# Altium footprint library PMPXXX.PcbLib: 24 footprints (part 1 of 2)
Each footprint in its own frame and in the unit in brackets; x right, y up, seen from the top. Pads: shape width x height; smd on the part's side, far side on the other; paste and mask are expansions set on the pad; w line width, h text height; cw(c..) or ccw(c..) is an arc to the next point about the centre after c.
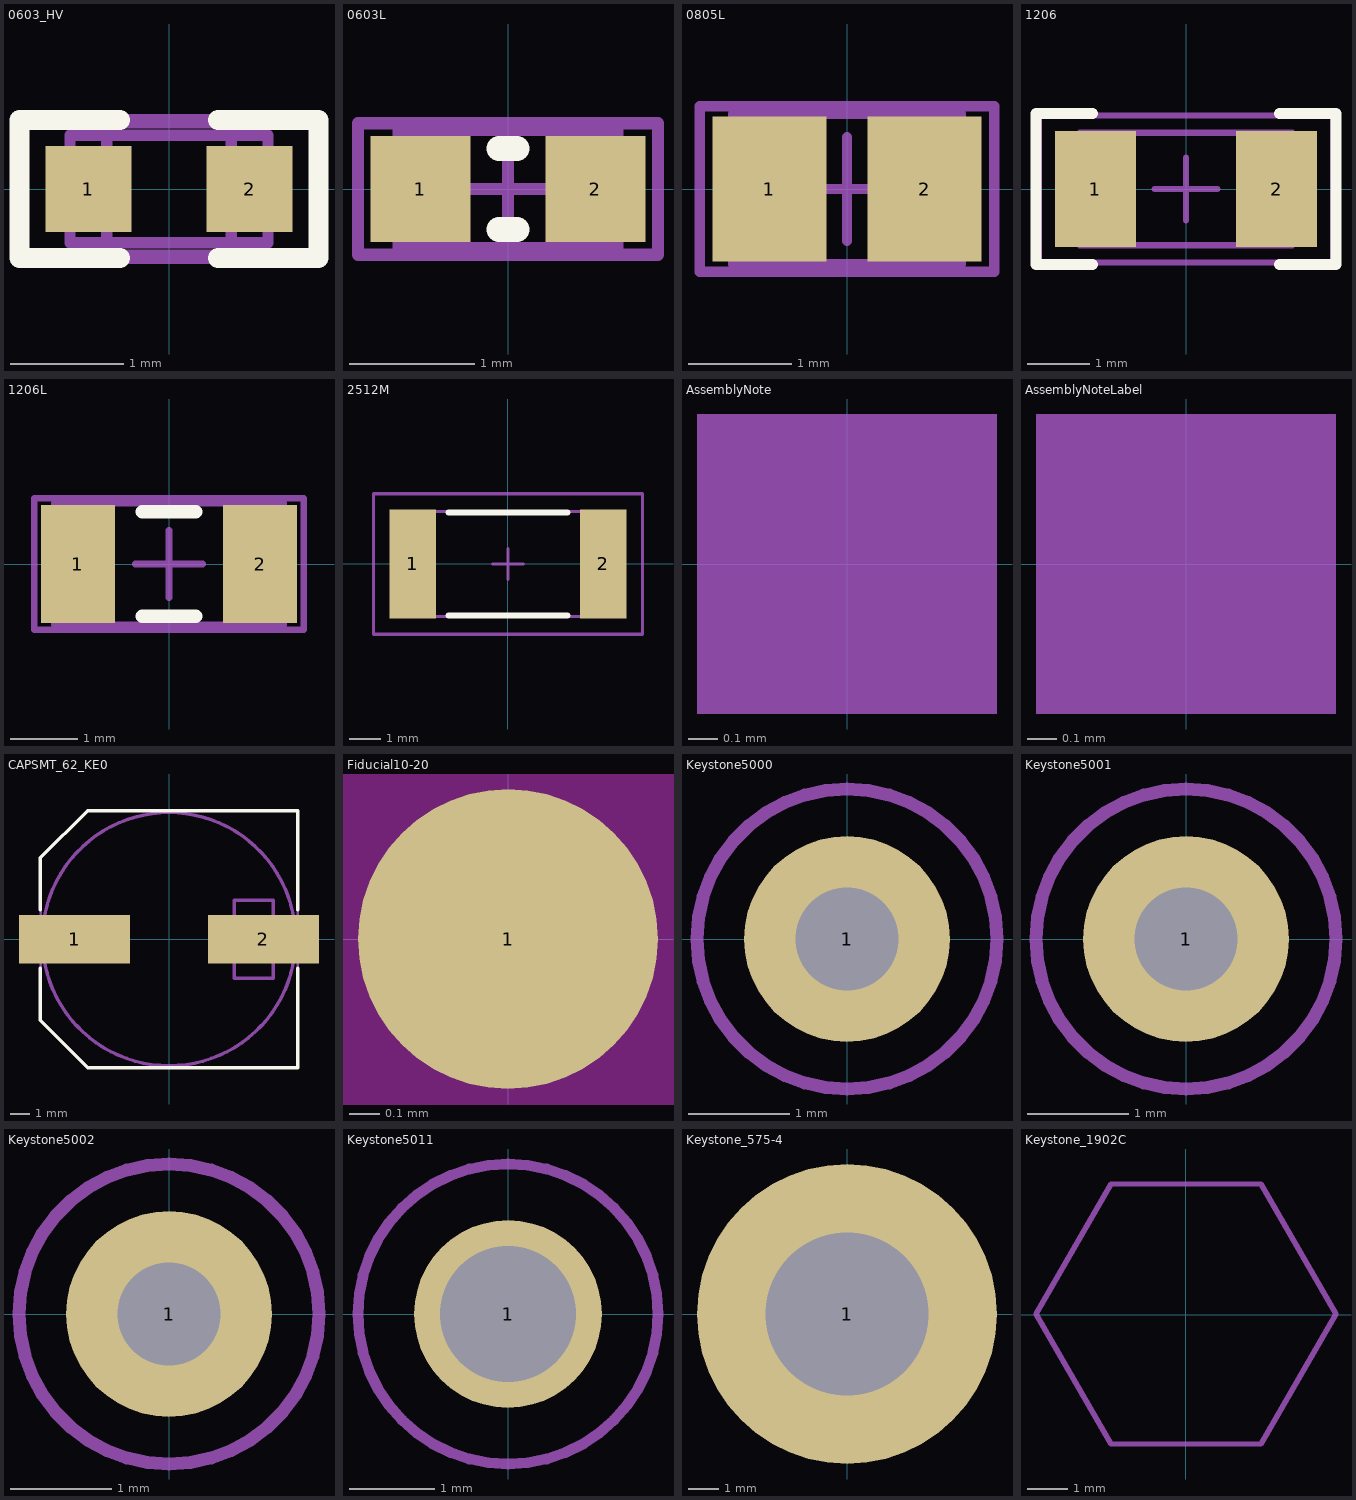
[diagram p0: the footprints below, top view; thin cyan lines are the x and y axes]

## 0603_HV [mil] "Ernesto recommended land pattern.  26 mil between pads."
height 37.4
pads (2):
  rect 30x30 smd: 1(-28,0) 2(28,0)
Top Overlay:
  lines w7: -17,-24 -52,-24 -52,0 -52,24 -17,24 ; 17,-24 52,-24 52,0 52,24 17,24
Mechanical 5:
  lines w5: -52.17,-23.62 -52.17,23.62 52.17,23.62 52.17,-23.62 -52.17,-23.62
  text ".Designator" at -45.82,-12.5 h25
Mechanical 13:
  lines w3.94: -21.65,-18.7 -21.65,18.7 ; 21.65,-18.7 21.65,18.7 ; -34.45,-18.7 -34.45,18.7 34.45,18.7 34.45,-18.7 -34.45,-18.7
3D body: height 33.46, standoff 0, extent 21.67,-18.68 34.43,18.68
3D body: height 33.46, standoff 0, extent -21.63,-18.68 21.63,18.68
3D body: height 33.46, standoff 0, extent -34.43,-18.68 -21.67,18.68

## 0603L [mm] "0603 from SM-752 data"
height 0.85
pads (2):
  rect 0.8x0.85 smd: 1(-0.7,0) 2(0.7,0)
Top Overlay:
  lines w0.2: -0.071,-0.325 0.071,-0.325 ; -0.071,0.325 0.071,0.325
Mechanical 5:
  lines w0.1: -1.2,-0.525 -1.2,0.525 1.2,0.525 1.2,-0.525 -1.2,-0.525
  text ".Designator" at -1.05,-0.275 h0.56
Mechanical 13:
  lines w0.1: -0.55,-0.475 -0.55,0.475 ; 0.55,-0.475 0.55,0.475 ; -0.875,-0.475 -0.875,0.475 0.875,0.475 0.875,-0.475 -0.875,-0.475
Mechanical 15:
  lines w0.1: -0.475,0 0.475,0 ; 0,-0.475 0,0.475 ; -1.2,-0.525 1.2,-0.525 1.2,0.525 -1.2,0.525 -1.2,-0.525
3D body: height 0.85, standoff 0, extent 0.551,-0.474 0.874,0.474
3D body: height 0.85, standoff 0, extent -0.549,-0.474 0.549,0.474
3D body: height 0.85, standoff 0, extent -0.874,-0.474 -0.551,0.474

## 0805L [mm] "0805 from SM-752 data"
height 1.1
pads (2):
  rect 1.1x1.4 smd: 1(-0.75,0) 2(0.75,0)
Mechanical 5:
  lines w0.1: -1.425,-0.8 1.425,-0.8 1.425,0.8 -1.425,0.8 -1.425,-0.8
  text ".Designator" at -1.2,-0.325 h0.64
Mechanical 13:
  lines w0.1: -0.65,-0.725 -0.65,0.725 ; 0.65,-0.725 0.65,0.725 ; -1.1,-0.725 1.1,-0.725 1.1,0.725 -1.1,0.725 -1.1,-0.725
Mechanical 15:
  lines w0.1: -0.5,0 0.5,0 ; 0,-0.5 0,0.5 ; -1.425,-0.8 -1.425,0.8 1.425,0.8 1.425,-0.8 -1.425,-0.8
3D body: height 1.1, standoff 0, extent -1.099,-0.724 -0.651,0.724
3D body: height 1.1, standoff 0, extent -0.649,-0.724 0.649,0.724
3D body: height 1.1, standoff 0, extent 0.651,-0.724 1.099,0.724

## 1206 [mm] "1206 from SM-752 data"
height 1.35
pads (2):
  rect 1.3x1.85 smd: 1(-1.45,0) 2(1.45,0)
Top Overlay:
  lines w0.178: -1.5,-1.21 -2.4,-1.21 -2.4,1.21 -1.5,1.21 ; 1.5,-1.21 2.4,-1.21 2.4,1.21 1.5,1.21
Mechanical 5:
  lines w0.1: -1.7,-0.9 -1.7,0.9 1.7,0.9 1.7,-0.9 -1.7,-0.9
  text ".Designator" at -1.475,-0.4 h0.81
Mechanical 13:
  lines w0.1: -1.2,-0.9 -1.2,0.9 ; 1.2,-0.9 1.2,0.9 ; -1.7,-0.9 -1.7,0.9 1.7,0.9 1.7,-0.9 -1.7,-0.9
Mechanical 15:
  lines w0.1: -0.5,0 0.5,0 ; 0,-0.5 0,0.5 ; -2.35,-1.175 -2.35,1.175 2.35,1.175 2.35,-1.175 -2.35,-1.175
3D body: height 1.35, standoff 0, extent 1.201,-0.899 1.699,0.899
3D body: height 1.35, standoff 0, extent -1.199,-0.899 1.199,0.899
3D body: height 1.35, standoff 0, extent -1.699,-0.899 -1.201,0.899

## 1206L [mm] "1206 from SM-752 data"
height 1.35
pads (2):
  rect 1.1x1.75 smd: 1(-1.35,0) 2(1.35,0)
Top Overlay:
  lines w0.2: -0.4,-0.775 0.4,-0.775 ; -0.4,0.775 0.4,0.775
Mechanical 5:
  lines w0.1: -1.7,-0.9 1.7,-0.9 1.7,0.9 -1.7,0.9 -1.7,-0.9
  text ".Designator" at -1.475,-0.4 h0.81
Mechanical 13:
  lines w0.1: -1.2,-0.9 -1.2,0.9 ; 1.2,-0.9 1.2,0.9 ; -1.7,-0.9 -1.7,0.9 1.7,0.9 1.7,-0.9 -1.7,-0.9
Mechanical 15:
  lines w0.1: -0.5,0 0.5,0 ; 0,-0.5 0,0.5 ; -2,-0.975 2,-0.975 2,0.975 -2,0.975 -2,-0.975
3D body: height 1.35, standoff 0, extent 1.201,-0.899 1.699,0.899
3D body: height 1.35, standoff 0, extent -1.199,-0.899 1.199,0.899
3D body: height 1.35, standoff 0, extent -1.699,-0.899 -1.201,0.899

## 2512M [mm] "Chip Resistor, Body 6.3x3.2mm, IPC Low Density"
height 0.71
pads (2):
  rect 1.5x3.5 smd: 1(-3.05,0) 2(3.05,0)
Top Overlay:
  lines w0.2: -1.9,-1.65 1.9,-1.65 ; -1.9,1.65 1.9,1.65
Mechanical 5:
  lines w0.1: -3.225,-1.675 3.225,-1.675 3.225,1.675 -3.225,1.675 -3.225,-1.675
  text ".Designator" at -1.85,-0.5 h1.02
Mechanical 13:
  lines w0.1: -2.463,-1.675 -2.463,1.675 ; 2.463,-1.675 2.463,1.675 ; -3.225,-1.675 3.225,-1.675 3.225,1.675 -3.225,1.675 -3.225,-1.675
Mechanical 15:
  lines w0.1: -0.5,0 0.5,0 ; 0,-0.5 0,0.5 ; -4.3,-2.25 4.3,-2.25 4.3,2.25 -4.3,2.25 -4.3,-2.25
3D body: height 0.71, standoff 0, extent -3.224,-1.674 -2.464,1.674
3D body: height 0.71, standoff 0, extent -2.462,-1.674 2.462,1.674
3D body: height 0.71, standoff 0, extent 2.464,-1.674 3.224,1.674

## AssemblyNote [mm] "Assembly Note"
Mechanical 5:
  rectangle: -0.508,-0.508 0.508,0.508
  text ".Designator" at -4.191,-0.508 h1.02
  text ".Comment" at 1.143,-0.508 h1.02

## AssemblyNoteLabel [mm] "Assembly Note for PCB Labels"
Mechanical 5:
  rectangle: -0.508,-0.508 0.508,0.508
  text "Install label in silkscreened box after final wash.  Text shall be 8 pt font. Text shall be per Table 1" at 1.143,-0.508 h1.02
  text ".Designator" at -4.191,-0.508 h1.02

## CAPSMT_62_KE0 [mm] "12.5 x 13.5mm:  Chemi-Con KE0"
height 14
pads (2):
  rect 5.7x2.5 smd: 1(-4.85,0) 2(4.85,0)
Top Overlay:
  lines w0.178: -6.6,-1.5 -6.6,-4.175 -4.175,-6.6 0,-6.6 6.6,-6.6 6.6,-1.5 ; -6.6,1.5 -6.6,4.175 -4.175,6.6 0,6.6 6.6,6.6 6.6,1.5
Mechanical 5:
  lines w0.127: -6.588,-4.163 -6.588,4.187 -4.163,6.612 0.012,6.612 6.612,6.612 6.612,-6.588 0.012,-6.588 -4.163,-6.588 -6.588,-4.163
  text ".Designator" at -1.524,-0.508 h1.02
Mechanical 13:
  circle w0.178: c0,0 r6.5
  lines w0.178: 3.35,-2 3.35,2 5.35,2 5.35,-2 3.35,-2
3D body: height 14, standoff 1, extent -6.51,-6.51 6.51,6.51
3D body: height 1, standoff 0, extent -6.601,-6.601 6.601,6.601
3D body: height 14, standoff 13.9, extent 3.35,-1.999 5.349,1.999

## Fiducial10-20 [mm]
pads (1):
  round 1 smd paste-0.5 mask+0.5: 1(0,0)
Keep-Out Layer:
  circle w1.178: c0,0 r0.5

## Keystone5000 [mil] "For Keystone 500x miniature loop terminals"
height 181.1
pads (1):
  round 80 hole 40: 1(0,0)
Mechanical 5:
  circle w5: c0,0 r58.31
  text ".Designator" at -45,-10 h30
3D body: height 181.97, standoff -118.11, extent -49,-49 49.04,49.24

## Keystone5001 [mil] "For Keystone 500x miniature loop terminals"
height 181.1
pads (1):
  round 80 hole 40: 1(0,0)
Mechanical 5:
  circle w5: c0,0 r58.31
  text ".Designator" at -45,-10 h30
3D body: height 181.97, standoff -118.11, extent -49,-49 49.04,49.24

## Keystone5002 [mil] "For Keystone 500x miniature loop terminals"
height 181.1
pads (1):
  round 80 hole 40: 1(0,0)
Mechanical 5:
  circle w5: c0,0 r58.31
  text ".Designator" at -45,-10 h30
3D body: height 181.97, standoff -118.11, extent -49,-49 49.04,49.23

## Keystone5011 [mil] "Keystone Multipurpose loops"
height 320
pads (1):
  round 87 hole 63: 1(0,0)
Mechanical 5:
  circle w5: c0,0 r69.46
  text ".Designator" at -55,-10 h30
3D body: height 318.9, standoff -125.98, extent -63,-63 62.74,62.49

## Keystone_575-4 [mm] "Banana Jack"
height 2.362
pads (1):
  round 10 hole 5.45: 1(0,0)
Mechanical 5:
  circle w0.127: c0,0 r4.887
  text ".Designator" at -1.397,-0.762 h1.52
3D body: height 2.36, standoff -5.5, extent -3.95,-3.95 3.919,3.934

## Keystone_1902C [mm] "Hex Standoff, 4-40 threaded, nylon"
height 12.7
Mechanical 5:
  lines w0.127: -3.69,0.012 -1.843,-3.188 1.852,-3.188 3.7,0.012 1.852,3.212 -1.843,3.212 -3.69,0.012
  text ".Designator" at -1.524,-0.508 h1.02
3D body: height 12.73, standoff 0.03, extent -3.682,-3.2 3.708,3.2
